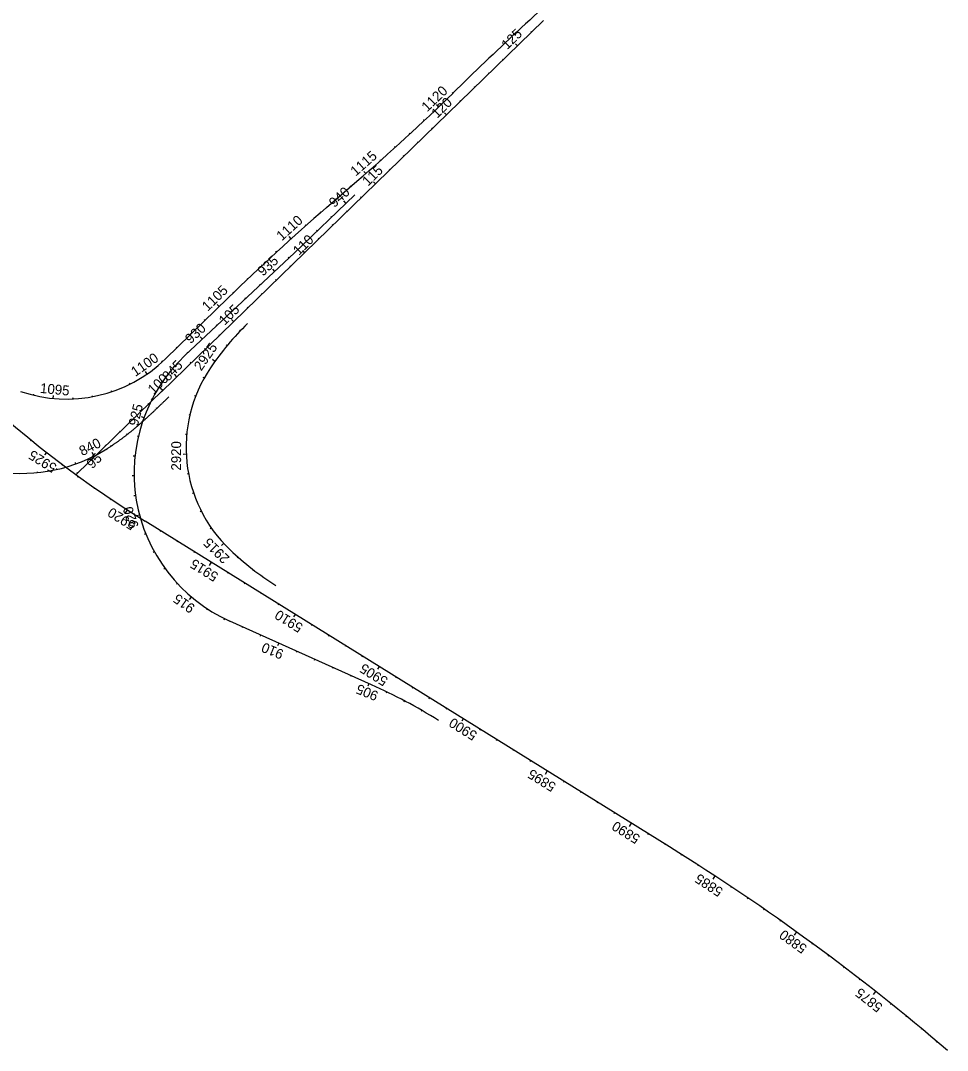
# Model space of a CAD drawing. Extents: x 448091 to 665917, y 1461380 to 1587607.
# Drawn here: x 486066 to 490751, y 1524457 to 1529663 of the extents above; entities that cross this region are included whole.
import ezdxf

# ---------------------------------------------------------------- set-up
doc = ezdxf.new("R2010")
doc.units = 0
doc.layers.add('TextShtNo', color=7, linetype='Continuous')
doc.layers.add('TextTitle', color=7, linetype='Continuous')

msp = doc.modelspace()

# ---------------------------------------------------------------- linework, layer by layer
at = {"layer": 'TextShtNo'}
for p, q in [((486779, 1527787.1), (488709.9, 1529663.1)), ((487612.3, 1528717.5), (487766.6, 1528851.1)), ((487450.9, 1528488.8), (487756.2, 1528781.5)), ((486898.8, 1527971.4), (487450.9, 1528488.8)), ((486799.1, 1527953), (487115.7, 1528261.5)), ((486347.3, 1527367.7), (486786.2, 1527794.1)), ((489346.7, 1525485.5), (486696.1, 1527132.7)), ((487839.8, 1526305.8), (487123.3, 1526627.5))]:
    msp.add_line(p, q, dxfattribs=at)
for centre, radius, start, end in [((498232, 1519205.8), 14192.2, 131.04246, 134.68518), ((480267, 1537515.3), 11459.2, 310.87892, 314.17342), ((489720.3, 1531999.2), 5729.6, 212.22426, 238.14093), ((495111.9, 1520053.3), 11459.2, 130.87892, 134.25023), ((488211.6, 1527103.8), 1432.4, 134.1735, 145.8317), ((487458.5, 1527374.2), 818.5, 133.1405, 245.8206), ((486299.3, 1528466.1), 716.2, 251.0257, 314.2502), ((487619, 1527506), 716.2, 145.8316, 226.3941), ((486068.8, 1528192.4), 818.5, 222.1128, 302.2473), ((488113, 1528024.6), 1432.4, 226.3941, 238.1409), ((486666.4, 1523692.3), 2864.8, 58.1412, 65.8206), ((483298.2, 1515752.7), 11459.2, 49.42926, 58.14093)]:
    msp.add_arc(centre, radius, start, end, dxfattribs=at)
msp.add_spline([(486815.6, 1527760.8), (486812.5, 1527757.8), (486807.9, 1527753.4), (486803.3, 1527748.9), (486798.7, 1527744.4), (486794.1, 1527739.9), (486789.5, 1527735.5), (486784.9, 1527731), (486780.2, 1527726.5), (486775.6, 1527722.1), (486771, 1527717.6), (486766.4, 1527713.2), (486761.7, 1527708.8), (486757.1, 1527704.3), (486752.4, 1527699.9), (486747.8, 1527695.5), (486743.1, 1527691.1), (486738.5, 1527686.6), (486733.8, 1527682.2), (486729.1, 1527677.9), (486724.4, 1527673.5), (486719.7, 1527669.1), (486715, 1527664.7), (486710.3, 1527660.4), (486705.6, 1527656.1), (486700.8, 1527651.7), (486696.1, 1527647.4), (486691.3, 1527643.1), (486686.5, 1527638.8), (486681.7, 1527634.6), (486676.9, 1527630.3), (486672.1, 1527626.1), (486667.3, 1527621.8), (486662.4, 1527617.6), (486657.6, 1527613.4), (486652.7, 1527609.3), (486647.8, 1527605.1), (486642.9, 1527601), (486638, 1527596.9), (486633, 1527592.8), (486628.1, 1527588.7), (486623.1, 1527584.6), (486618.1, 1527580.6), (486613.1, 1527576.6), (486608.1, 1527572.6), (486603, 1527568.6), (486598, 1527564.7), (486592.9, 1527560.8), (486587.8, 1527556.9), (486582.6, 1527553), (486577.5, 1527549.2), (486572.3, 1527545.3), (486567.1, 1527541.6), (486561.9, 1527537.8), (486556.7, 1527534.1), (486551.5, 1527530.4), (486546.2, 1527526.7), (486540.9, 1527523.1), (486535.6, 1527519.5), (486530.3, 1527515.9), (486524.9, 1527512.4), (486519.5, 1527508.9), (486514.1, 1527505.4), (486508.7, 1527502), (486503.3, 1527498.6), (486497.8, 1527495.2), (486496.7, 1527494.5)], degree=3, dxfattribs=at)
at = {"layer": 'TextTitle'}
for p, q in [((488646, 1529608), (488649.5, 1529604.4)), ((488567.3, 1529545.5), (488577.8, 1529534.7)), ((488502.6, 1529468.6), (488506.1, 1529465.1)), ((488430.8, 1529399), (488434.3, 1529395.4)), ((488359.1, 1529329.3), (488362.6, 1529325.7)), ((488247.4, 1529300.2), (488251.6, 1529296)), ((488179.8, 1529226.8), (488169.5, 1529237.7)), ((488287.4, 1529259.6), (488290.9, 1529256)), ((488107.2, 1529158.1), (488103.8, 1529161.7)), ((488208.7, 1529197.1), (488219.2, 1529186.3)), ((488144, 1529120.2), (488147.4, 1529116.6)), ((488034, 1529090), (488030.6, 1529093.6)), ((487960.2, 1529022.5), (487956.8, 1529026.2)), ((488072.2, 1529050.5), (488075.7, 1529047)), ((487885.7, 1528955.7), (487882.4, 1528959.4)), ((488000.5, 1528980.9), (488004, 1528977.3)), ((487810.8, 1528889.5), (487800.9, 1528900.8)), ((487928.8, 1528911.2), (487932.3, 1528907.6)), ((487860.5, 1528837.9), (487850.8, 1528848)), ((487735.3, 1528824), (487732, 1528827.8)), ((487659.6, 1528758.5), (487656.4, 1528762.3)), ((487697.9, 1528751.4), (487710.8, 1528738)), ((487785.3, 1528771.8), (487788.8, 1528768.2)), ((487584.1, 1528693), (487580.8, 1528696.8)), ((487713.6, 1528702.1), (487717.1, 1528698.5)), ((487634.4, 1528673.2), (487638.6, 1528668.8)), ((487509, 1528627), (487505.6, 1528630.8)), ((487562.2, 1528604), (487566.4, 1528599.7)), ((487641.9, 1528632.4), (487645.4, 1528628.9)), ((487434.4, 1528560.4), (487424.4, 1528571.5)), ((487490.1, 1528534.7), (487494.3, 1528530.4)), ((487570.2, 1528562.8), (487573.7, 1528559.2)), ((487360.5, 1528493), (487357.1, 1528496.7)), ((487491.5, 1528500.3), (487501.9, 1528489.5)), ((487287.1, 1528425.1), (487283.7, 1528428.7)), ((487419.2, 1528467.3), (487423.3, 1528462.9)), ((487339.4, 1528406.2), (487350.3, 1528394.5)), ((487426.7, 1528423.4), (487430.2, 1528419.8)), ((487214.4, 1528356.5), (487210.9, 1528360.1)), ((487273.3, 1528330.5), (487277.4, 1528326.1)), ((487358.5, 1528350.1), (487355, 1528353.7)), ((487142.2, 1528287.2), (487138.7, 1528290.8)), ((487286.8, 1528280.4), (487283.3, 1528284)), ((487070.6, 1528217.5), (487060.1, 1528228.2)), ((487200.3, 1528262.1), (487204.4, 1528257.8)), ((487127.3, 1528193.8), (487131.4, 1528189.4)), ((487211.6, 1528214.3), (487215, 1528210.8)), ((486998.9, 1528147.7), (486995.4, 1528151.3)), ((487054.4, 1528125.4), (487058.5, 1528121)), ((487132.9, 1528151.8), (487143.3, 1528141.1)), ((486927.3, 1528077.9), (486923.8, 1528081.5)), ((486974.6, 1528064.3), (486985.5, 1528052.6)), ((487068.1, 1528075), (487071.6, 1528071.4)), ((487172.3, 1528098.2), (487176.6, 1528094)), ((487110, 1528019.4), (487106.2, 1528022.6)), ((486855.7, 1528008.2), (486852.2, 1528011.7)), ((486912.5, 1527984.3), (486909.7, 1527987.4)), ((486996.4, 1528005.3), (486999.9, 1528001.7)), ((486783.8, 1527938.6), (486780.4, 1527942.3)), ((486842.4, 1527913), (486838.6, 1527916.3)), ((486928.1, 1527932), (486923.5, 1527936.8)), ((486928.1, 1527931.6), (486925.1, 1527934.6)), ((487048.8, 1527940.3), (487036.7, 1527949.1)), ((486705.7, 1527876.3), (486697.2, 1527888.7)), ((486856.4, 1527861.9), (486843.8, 1527874.9)), ((486856.4, 1527861.9), (486853.4, 1527864.9)), ((486994.4, 1527856.5), (486990.1, 1527858.9)), ((486619.7, 1527825.5), (486617.4, 1527830)), ((486781.3, 1527833.9), (486777.2, 1527836.7)), ((486133, 1527769.4), (486134.1, 1527774.3)), ((486231.5, 1527753.1), (486233, 1527768)), ((486331.4, 1527750.6), (486331.2, 1527755.6)), ((486430.7, 1527762), (486429.8, 1527766.9)), ((486527.4, 1527787.1), (486525.8, 1527791.9)), ((486784.7, 1527792.7), (486774.2, 1527803.4)), ((486946.1, 1527768.3), (486951.7, 1527766.1)), ((486709.5, 1527726.6), (486713, 1527723)), ((486730.4, 1527748), (486725.9, 1527750.3)), ((486755.5, 1527702.8), (486752.6, 1527705.9)), ((486637.8, 1527656.9), (486641.2, 1527653.3)), ((486676.1, 1527661.6), (486690.2, 1527656.4)), ((486916.2, 1527672.1), (486922, 1527670.7)), ((486682.1, 1527634.9), (486679.3, 1527638.1)), ((486566, 1527587.2), (486569.5, 1527583.6)), ((486605.6, 1527570.6), (486602.9, 1527574)), ((486661.6, 1527560.7), (486656.7, 1527561.8)), ((486899.9, 1527572.6), (486905.9, 1527572.1)), ((486120, 1527542.1), (486116.9, 1527538.2)), ((486494.3, 1527517.5), (486497.8, 1527513.9)), ((486524.5, 1527512.1), (486522.2, 1527515.7)), ((486189.1, 1527468.1), (486198.3, 1527479.9)), ((486415.6, 1527455), (486433, 1527437.1)), ((486438.1, 1527461.9), (486428.8, 1527480.2)), ((486635.5, 1527463.3), (486641.4, 1527462.6)), ((486887.6, 1527471.3), (486903.6, 1527472.2)), ((486250.4, 1527394.3), (486249.4, 1527398.4)), ((486274.7, 1527415.1), (486277.8, 1527419.1)), ((486346.3, 1527422.4), (486343.9, 1527429)), ((486346.3, 1527422.4), (486344.8, 1527426.4)), ((486151.8, 1527378.1), (486151.3, 1527382.4)), ((486350.9, 1527378.1), (486354.4, 1527374.6)), ((486355.3, 1527355.7), (486358.2, 1527359.7)), ((486630.8, 1527362.7), (486636.8, 1527362.8)), ((486909.4, 1527371.8), (486915.3, 1527373)), ((486436.8, 1527297.7), (486439.7, 1527301.8)), ((486522.2, 1527245.2), (486519.4, 1527241.1)), ((486638.4, 1527262.3), (486644.3, 1527263.1)), ((486935, 1527274.4), (486940.6, 1527276.4)), ((486605.6, 1527190.1), (486594.8, 1527173.4)), ((486973.9, 1527181.4), (486979.2, 1527184.2)), ((486651.8, 1527160.6), (486667.3, 1527164.7)), ((486690, 1527136.5), (486687.4, 1527132.3)), ((486772.3, 1527079.5), (486775, 1527083.7)), ((487025.3, 1527094.8), (487030.2, 1527098.3)), ((486693, 1527067.5), (486698.6, 1527069.8)), ((486859.9, 1527030.9), (486857.3, 1527026.7)), ((486736.2, 1526976.6), (486741.5, 1526979.5)), ((486944.8, 1526978.2), (486942.2, 1526973.9)), ((487081.7, 1527010.1), (487092.7, 1527020.3)), ((487029.8, 1526925.4), (487019.2, 1526908.4)), ((487164.8, 1526951), (487161.4, 1526947.3)), ((486790, 1526891.6), (486794.9, 1526895.1)), ((487114.7, 1526872.6), (487112.1, 1526868.3)), ((487242, 1526887.5), (487238.9, 1526883.5)), ((486853.8, 1526813.7), (486858.2, 1526817.8)), ((487199.6, 1526819.8), (487197, 1526815.6)), ((487323.4, 1526829.5), (487320.6, 1526825.3)), ((487284.6, 1526767), (487281.9, 1526762.8)), ((486920.2, 1526736.5), (486930.5, 1526748.7)), ((487369.5, 1526714.2), (487366.9, 1526710)), ((487007.4, 1526684), (487010.7, 1526689.1)), ((487454.4, 1526661.5), (487446.5, 1526648.7)), ((487094.9, 1526634.2), (487097.5, 1526639.6)), ((487539.4, 1526608.7), (487536.7, 1526604.4)), ((487188.5, 1526598.2), (487186.1, 1526592.7)), ((487279.8, 1526557.2), (487277.3, 1526551.7)), ((487624.3, 1526555.9), (487621.7, 1526551.6)), ((487371, 1526516.3), (487364.4, 1526501.7)), ((487709.2, 1526503.1), (487706.6, 1526498.9)), ((487462.2, 1526475.3), (487459.8, 1526469.8)), ((487794.2, 1526450.3), (487791.5, 1526446.1)), ((487553.4, 1526434.3), (487551, 1526428.9)), ((487644.7, 1526393.4), (487642.2, 1526387.9)), ((487735.9, 1526352.4), (487733.4, 1526346.9)), ((487879.1, 1526397.5), (487871.2, 1526384.8)), ((487827.1, 1526311.5), (487821, 1526297.8)), ((487964, 1526344.8), (487961.4, 1526340.5)), ((487915.6, 1526264.8), (487917.8, 1526269.3)), ((488049, 1526292), (488046.3, 1526287.7)), ((488004.6, 1526219.7), (488007, 1526224.1)), ((488131.3, 1526234.9), (488133.9, 1526239.2)), ((488092, 1526171.4), (488094.3, 1526175.5)), ((488218.9, 1526186.4), (488216.2, 1526182.2)), ((488303.8, 1526133.6), (488295.9, 1526120.9)), ((488388.7, 1526080.8), (488386.1, 1526076.6)), ((488473.7, 1526028.1), (488471, 1526023.8)), ((488558.6, 1525975.3), (488556, 1525971)), ((488643.5, 1525922.5), (488640.9, 1525918.2)), ((488728.5, 1525869.7), (488717.9, 1525852.7)), ((488813.4, 1525816.9), (488810.8, 1525812.7)), ((488898.3, 1525764.1), (488895.7, 1525759.9)), ((488983.3, 1525711.4), (488980.6, 1525707.1)), ((489068.2, 1525658.6), (489065.6, 1525654.3)), ((489153.1, 1525605.8), (489142.6, 1525588.8)), ((489238.1, 1525553), (489235.4, 1525548.8)), ((489323, 1525500.2), (489320.4, 1525496)), ((489407.8, 1525447.3), (489405.2, 1525443)), ((489492.2, 1525393.6), (489489.5, 1525389.4)), ((489576.1, 1525339.2), (489565.1, 1525322.4)), ((489659.5, 1525284), (489656.7, 1525279.8)), ((489742.4, 1525228.1), (489739.6, 1525224)), ((489824.9, 1525171.5), (489822, 1525167.4)), ((489906.8, 1525114.2), (489903.9, 1525110.1)), ((489988.3, 1525056.2), (489976.6, 1525040)), ((490069.2, 1524997.5), (490066.2, 1524993.4)), ((490149.6, 1524938), (490146.6, 1524934)), ((490229.5, 1524877.9), (490226.5, 1524873.9)), ((490308.9, 1524817), (490305.8, 1524813.1)), ((490387.7, 1524755.5), (490375.3, 1524739.8)), ((490466, 1524693.3), (490462.9, 1524689.4)), ((490543.8, 1524630.4), (490540.6, 1524626.5)), ((490620.9, 1524566.9), (490617.8, 1524563)), ((490697.6, 1524502.6), (490694.4, 1524498.8))]:
    msp.add_line(p, q, dxfattribs=at)

# ---------------------------------------------------------------- texts
for s, rotation, p in [('125', 44.1839, (488525.8, 1529513.7)), ('1120', 43.6715, (488121.7, 1529199.4)), ('120', 44.1835, (488172, 1529166.3)), ('1115', 41.1715, (487760.5, 1528874.2)), ('115', 44.1839, (487822.4, 1528823.3)), ('940', 42.3336, (487652.5, 1528715.1)), ('1110', 42.0656, (487386.9, 1528547)), ('110', 44.1834, (487472.3, 1528472.5)), ('935', 42.3336, (487291.6, 1528368.3)), ('1105', 44.2502, (487012.2, 1528190.7)), ('105', 44.1844, (487097.5, 1528119.7)), ('930', 42.3336, (486925.3, 1528026.3)), ('2925', 55.4905, (486979.7, 1527889)), ('1100', 34.5687, (486646.3, 1527861.3)), ('845', 45.8736, (486812.5, 1527837)), ('100', 44.1734, (486738.2, 1527770.3)), ('1095', 354.5687, (486163.2, 1527781.2)), ('925', 75.9392, (486659, 1527610)), ('840', 26.8159, (486378.3, 1527460.6)), ('2920', 89.8865, (486877.6, 1527388.3)), ('5925', 148.1409, (486253.8, 1527416.2)), ('95', 44.1734, (486428.8, 1527394.1)), ('5920', 148.1409, (486653.5, 1527126)), ('920', 108.6973, (486664.9, 1527106)), ('2915', 135.3474, (487126.6, 1526948.4)), ('5915', 148.1409, (487070.5, 1526866)), ('915', 144.5447, (486952.3, 1526704.1)), ('5910', 148.1409, (487498.3, 1526608.2)), ('910', 157.614, (487400.8, 1526478.4)), ('5905', 148.1409, (487927.7, 1526337.6)), ('905', 157.614, (487879.1, 1526268.1)), ('5900', 148.1409, (488378.8, 1526062.9)), ('5895', 148.1409, (488776.9, 1525803.6)), ('5890', 148.1409, (489202.2, 1525540.5)), ('5885', 146.7805, (489621.3, 1525272.1)), ('5880', 144.2805, (490045.7, 1524983.4)), ('5875', 141.7805, (490428, 1524684.6))]:
    msp.add_text(s, height=50, rotation=rotation, dxfattribs=at).set_placement(p)

doc.saveas('drawing.dxf')
